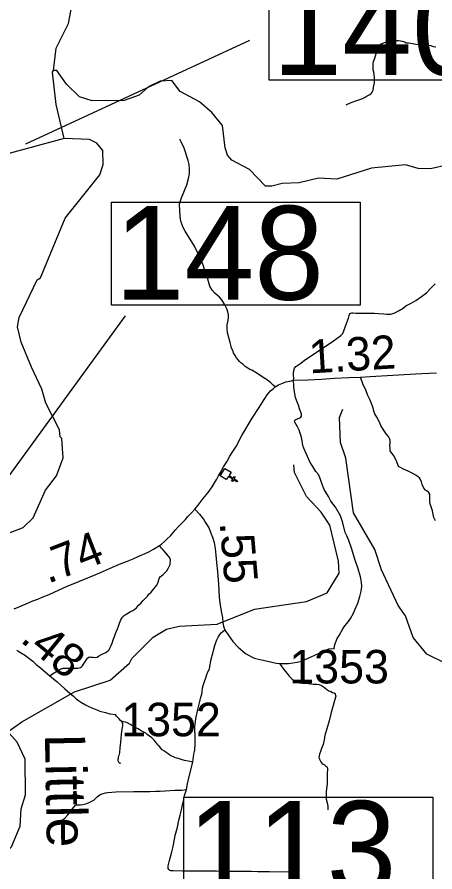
# Model space of a CAD drawing. Extents: x 2290615 to 2522933, y 819489 to 1012715.
# Drawn here: x 2328328 to 2334565, y 903675 to 916430 of the extents above; entities that cross this region are included whole.
import ezdxf

# ---------------------------------------------------------------- set-up
doc = ezdxf.new("R2010")
doc.units = 0
for name, color, linetype in [('Exist Cultural Church CELL', 7, 'Continuous'), ('Exist Hydrographic Creek Single Shore', 7, 'Continuous'), ('Exist Hydrographic Creek Single Shore Label', 7, 'Continuous'), ('Exist Hydrographic Misc Water Feature', 7, 'Continuous'), ('Exist Road Non-System Type 51', 7, 'Continuous'), ('Exist Road Secondary Mileage Hundredths English Label', 7, 'Continuous'), ('Exist Road Secondary Structure Standard Bridge Number Label', 7, 'Continuous'), ('Exist Road Secondary Type 51 Attributed', 7, 'Continuous'), ('Exist Road Secondary Type 51 Number Label', 7, 'Continuous')]:
    doc.layers.add(name, color=color, linetype=linetype)

msp = doc.modelspace()

# ---------------------------------------------------------------- linework, layer by layer
at = {"layer": 'Exist Cultural Church CELL'}
msp.add_lwpolyline([(2331521, 909638), (2331491, 909590), (2331555, 909549), (2331572, 909576), (2331585, 909568), (2331568, 909541), (2331619, 909508), (2331610, 909495), (2331560, 909527), (2331542, 909500), (2331529, 909509), (2331546, 909536), (2331482, 909577), (2331451, 909528), (2331361, 909585), (2331431, 909695)], close=True, dxfattribs=at)
at = {"layer": 'Exist Hydrographic Creek Single Shore'}
for points in [[(2328871, 915633), (2328909, 915966), (2329097, 916335), (2329199, 916894), (2329162, 917243), (2329102, 917352), (2328866, 917609), (2328739, 917846), (2328746, 917965), (2328828, 918057), (2329135, 918227), (2329382, 918404), (2329422, 918482), (2329413, 918613), (2329355, 918679)], [(2329032, 914619), (2328909, 915126), (2328854, 915609), (2328871, 915633)], [(2329032, 914619), (2328169, 914387)], [(2328335, 911807), (2328360, 911946), (2328629, 912508), (2328679, 912540), (2329044, 913428), (2329562, 914076), (2329611, 914232), (2329608, 914442), (2329516, 914550), (2329407, 914605), (2329032, 914619)], [(2327886, 908608), (2328417, 908813), (2328566, 908957), (2328753, 909369), (2328917, 909585), (2329014, 909852), (2328994, 910143), (2328969, 910169), (2328959, 910270), (2328755, 910668), (2328695, 910876), (2328541, 911208), (2328387, 911579), (2328335, 911807)], [(2325675, 904352), (2326165, 904408), (2326674, 904406), (2327058, 904326), (2327367, 904178), (2327812, 903859), (2327979, 903885), (2328145, 903954), (2328243, 904047), (2328374, 904357), (2328387, 904614), (2328452, 904823), (2328446, 905358), (2328327, 905613), (2328209, 905746), (2328208, 905778)]]:
    msp.add_lwpolyline(points, dxfattribs=at)
at = {"layer": 'Exist Hydrographic Misc Water Feature'}
for points in [[(2331799, 914155), (2331534, 914295), (2331467, 914371), (2331432, 914478), (2331395, 914811), (2331235, 915008), (2331050, 915164), (2330764, 915320), (2330638, 915486), (2330464, 915475), (2330290, 915389), (2330149, 915265), (2329925, 915187), (2329449, 915181), (2329258, 915238), (2329064, 915427), (2328920, 915635), (2328871, 915633)], [(2335149, 914154), (2334940, 914234), (2334765, 914224), (2334499, 914164), (2334316, 914169), (2334124, 914224), (2333616, 914177), (2333102, 914011), (2332826, 914026), (2332536, 913955), (2332286, 913945), (2332128, 913909), (2332036, 913908), (2331799, 914155)], [(2335796, 906582), (2335621, 906647), (2335136, 906772), (2334728, 906785), (2334443, 906924), (2334240, 907172), (2334128, 907495), (2334017, 907651), (2333769, 908180), (2333666, 908487), (2333351, 909035), (2333233, 909848), (2333155, 910081), (2333142, 910455), (2333191, 910581)], [(2331870, 907593), (2332650, 907710), (2332957, 907838), (2333137, 908131), (2333126, 908314), (2332995, 908847), (2332868, 909045), (2332648, 909276), (2332469, 909633), (2332459, 909747)], [(2328208, 905778), (2328398, 905914), (2329185, 906363), (2329716, 906536), (2330005, 906791), (2330038, 906858), (2330359, 907176), (2330558, 907296), (2330749, 907340), (2331315, 907370), (2331870, 907593)]]:
    msp.add_lwpolyline(points, dxfattribs=at)
at = {"layer": 'Exist Road Non-System Type 51'}
for points in [[(2333241, 915123), (2333313, 915154), (2333401, 915185), (2333475, 915210), (2333522, 915236), (2333553, 915253), (2333582, 915268), (2333609, 915285), (2333620, 915296), (2333630, 915312), (2333641, 915342), (2333648, 915383), (2333662, 915447), (2333664, 915483), (2333662, 915530), (2333657, 915576), (2333655, 915610), (2333643, 915641), (2333642, 915667), (2333642, 915695), (2333643, 915734), (2333649, 915769), (2333656, 915791), (2333666, 915816), (2333687, 915889), (2333705, 915949), (2333724, 916000), (2333751, 916028), (2333786, 916041), (2333815, 916052), (2333829, 916055), (2333869, 916059), (2333891, 916066), (2333914, 916070), (2333932, 916077), (2333949, 916080), (2333964, 916081), (2333988, 916083), (2334020, 916081), (2334049, 916078), (2334077, 916070), (2334109, 916060), (2334137, 916048), (2334173, 916046), (2334229, 916037), (2334282, 916028), (2334342, 916021), (2334390, 916016), (2334459, 916010), (2334502, 916004), (2334537, 915993), (2334577, 915986)], [(2332180, 910914), (2332150, 910937), (2332112, 910977), (2332053, 911020), (2332003, 911053), (2331908, 911118), (2331830, 911162), (2331804, 911174), (2331774, 911192), (2331733, 911217), (2331695, 911251), (2331667, 911269), (2331646, 911290), (2331626, 911318), (2331604, 911346), (2331582, 911380), (2331559, 911421), (2331547, 911453), (2331528, 911491), (2331520, 911535), (2331508, 911575), (2331495, 911631), (2331471, 911718), (2331465, 911786), (2331464, 911818), (2331465, 911840), (2331476, 911884), (2331482, 911938), (2331482, 911986), (2331475, 912034), (2331459, 912079), (2331430, 912137), (2331384, 912209), (2331347, 912252), (2331281, 912313), (2331242, 912357), (2331207, 912413), (2331164, 912552), (2331092, 912773), (2330975, 913014), (2330839, 913236), (2330808, 913290), (2330777, 913368), (2330767, 913416), (2330762, 913462), (2330756, 913534), (2330752, 913642), (2330780, 913734), (2330860, 913929), (2330892, 914041), (2330899, 914099), (2330901, 914163), (2330894, 914229), (2330881, 914292), (2330821, 914474), (2330778, 914571), (2330758, 914607)], [(2333724, 912008), (2333804, 912004), (2333847, 911998), (2333867, 911996), (2333886, 911996), (2333902, 911996), (2333924, 912002), (2333965, 912018), (2334031, 912051), (2334090, 912088), (2334133, 912121), (2334208, 912163), (2334278, 912202), (2334363, 912259), (2334437, 912317), (2334510, 912388), (2334549, 912431), (2334571, 912451)], [(2332243, 906786), (2332302, 906784), (2332378, 906784), (2332507, 906804), (2332573, 906821), (2332685, 906868), (2332772, 906907), (2332839, 906941), (2332929, 906981), (2332983, 907005), (2333027, 907008), (2333062, 907005), (2333067, 907049), (2333082, 907093), (2333107, 907158), (2333137, 907202), (2333191, 907301), (2333221, 907347), (2333274, 907410), (2333306, 907456), (2333349, 907535), (2333370, 907585), (2333413, 907687), (2333442, 907784), (2333463, 907866), (2333472, 907936), (2333469, 907998), (2333452, 908076), (2333417, 908195), (2333367, 908343), (2333321, 908504), (2333282, 908621), (2333250, 908688), (2333227, 908739), (2333189, 908884), (2333155, 908990), (2333080, 909119), (2333013, 909206), (2332974, 909275), (2332912, 909383), (2332875, 909470), (2332853, 909544), (2332826, 909604), (2332789, 909651), (2332740, 909723), (2332704, 909782), (2332665, 909872), (2332642, 909919), (2332609, 909997), (2332595, 910039), (2332576, 910137), (2332565, 910194), (2332540, 910268), (2332516, 910314), (2332472, 910387), (2332469, 910405), (2332473, 910418), (2332488, 910428), (2332549, 910448), (2332564, 910460), (2332572, 910475), (2332572, 910503), (2332564, 910534), (2332545, 910585), (2332527, 910638), (2332503, 910698), (2332484, 910755), (2332473, 910808), (2332466, 910875), (2332459, 910924), (2332455, 911011), (2332459, 911044), (2332456, 911080), (2332456, 911110), (2332460, 911158), (2332467, 911190), (2332488, 911217), (2332563, 911265), (2332620, 911311), (2332764, 911403), (2332904, 911499), (2333033, 911586), (2333161, 911680), (2333189, 911710), (2333226, 911801), (2333252, 911875), (2333273, 911939), (2333286, 911978), (2333288, 911990), (2333298, 912006), (2333308, 912010), (2333324, 912016), (2333345, 912016), (2333386, 912012), (2333443, 912014), (2333490, 912012), (2333537, 912010), (2333580, 912010), (2333663, 912010), (2333724, 912008)], [(2333899, 910116), (2333888, 910143), (2333872, 910170), (2333835, 910211), (2333798, 910269), (2333760, 910335), (2333739, 910387), (2333699, 910461), (2333668, 910511), (2333658, 910535), (2333638, 910609), (2333619, 910663), (2333594, 910725), (2333563, 910786), (2333529, 910876), (2333496, 910943), (2333456, 911059)], [(2334574, 908912), (2334550, 908963), (2334530, 909063), (2334491, 909181), (2334489, 909236), (2334490, 909310), (2334468, 909340), (2334425, 909371), (2334401, 909399), (2334376, 909458), (2334366, 909493), (2334348, 909529), (2334333, 909554), (2334303, 909576), (2334280, 909593), (2334237, 909618), (2334166, 909654), (2334094, 909685), (2334039, 909713), (2334023, 909724), (2334013, 909752), (2333985, 909819), (2333954, 909884), (2333899, 909960), (2333896, 910001), (2333892, 910034), (2333896, 910076), (2333899, 910116)], [(2328818, 906600), (2328856, 906628), (2328955, 906689), (2328995, 906708), (2329007, 906711), (2329018, 906713), (2329041, 906714), (2329081, 906715), (2329112, 906713), (2329140, 906712), (2329180, 906713), (2329211, 906713), (2329236, 906715), (2329256, 906722), (2329274, 906727), (2329289, 906736), (2329304, 906752), (2329318, 906775), (2329350, 906817), (2329381, 906863), (2329397, 906878), (2329410, 906883), (2329427, 906881), (2329462, 906877), (2329494, 906875), (2329522, 906881), (2329545, 906892), (2329586, 906920), (2329618, 906934), (2329644, 906944), (2329666, 906959), (2329678, 906969), (2329692, 906981), (2329702, 906989), (2329713, 907011), (2329733, 907051), (2329750, 907101), (2329764, 907138), (2329781, 907188), (2329797, 907230), (2329824, 907304), (2329840, 907344), (2329857, 907388), (2329875, 907435), (2329891, 907459), (2329902, 907475), (2329926, 907499), (2329958, 907521), (2329980, 907534), (2330023, 907560), (2330055, 907576), (2330083, 907595), (2330109, 907617), (2330142, 907653), (2330176, 907686), (2330208, 907724), (2330239, 907757), (2330274, 907789), (2330296, 907817), (2330328, 907851), (2330350, 907874), (2330370, 907898), (2330395, 907928), (2330413, 907954), (2330432, 907998), (2330446, 908053), (2330462, 908077), (2330487, 908097), (2330507, 908113), (2330533, 908136), (2330550, 908151), (2330565, 908168), (2330584, 908202), (2330600, 908230), (2330612, 908260), (2330615, 908284), (2330619, 908310), (2330619, 908330), (2330613, 908348), (2330607, 908362), (2330536, 908447), (2330503, 908487), (2330483, 908507), (2330453, 908544)], [(2330951, 905310), (2330968, 905431), (2330979, 905493), (2330983, 905525), (2330987, 905553), (2330988, 905593), (2330988, 905629), (2330987, 905663), (2330985, 905705), (2330985, 905735), (2330982, 905771), (2330982, 905809), (2330981, 905843), (2330985, 905877), (2330989, 905919), (2330998, 905965), (2331008, 906011), (2331015, 906049), (2331027, 906099), (2331034, 906136), (2331046, 906180), (2331057, 906220), (2331071, 906282), (2331085, 906327), (2331092, 906364), (2331097, 906423), (2331103, 906456), (2331118, 906500), (2331130, 906529), (2331140, 906557), (2331149, 906585), (2331161, 906619), (2331176, 906658), (2331188, 906681), (2331200, 906710), (2331209, 906763), (2331214, 906797), (2331219, 906829), (2331236, 906884), (2331241, 906904), (2331245, 906919), (2331248, 906936), (2331258, 906978), (2331278, 907052), (2331294, 907097), (2331309, 907138), (2331328, 907180), (2331354, 907218), (2331373, 907241), (2331397, 907263), (2331428, 907289)], [(2332243, 906786), (2332270, 906752), (2332293, 906715), (2332330, 906671), (2332357, 906633), (2332391, 906597), (2332434, 906553), (2332470, 906527), (2332507, 906510), (2332541, 906498), (2332590, 906491), (2332671, 906484), (2332752, 906478), (2332800, 906478), (2332836, 906472), (2332871, 906455), (2332916, 906425), (2332949, 906397), (2332980, 906379), (2333010, 906366), (2333037, 906354), (2333061, 906346), (2333075, 906335), (2333078, 906324), (2333081, 906312), (2333084, 906296), (2333081, 906284), (2333070, 906245), (2333036, 906122), (2333010, 906035), (2332985, 905931), (2332949, 905809), (2332926, 905728), (2332918, 905684), (2332918, 905669), (2332913, 905646), (2332901, 905602), (2332895, 905574), (2332884, 905540), (2332874, 905514), (2332859, 905472), (2332843, 905430), (2332836, 905403), (2332833, 905385), (2332836, 905371), (2332840, 905355), (2332850, 905336), (2332862, 905316), (2332878, 905298), (2332899, 905284), (2332918, 905271), (2332933, 905259), (2332944, 905249), (2332955, 905237), (2332960, 905218), (2332963, 905200), (2332957, 905155), (2332958, 905086), (2332958, 905035), (2332954, 904988), (2332943, 904874), (2332941, 904785), (2332943, 904759), (2332957, 904703), (2332966, 904656), (2332968, 904599)], [(2329872, 905934), (2329852, 905957), (2329832, 905981), (2329811, 905999), (2329799, 906022)], [(2329872, 905934), (2329889, 905912), (2329897, 905900), (2329900, 905893), (2329900, 905879), (2329900, 905856), (2329891, 905803), (2329882, 905730), (2329878, 905670), (2329871, 905608), (2329862, 905530), (2329854, 905451), (2329846, 905413), (2329838, 905391), (2329834, 905367), (2329832, 905350), (2329832, 905335), (2329836, 905325), (2329841, 905315), (2329846, 905307), (2329853, 905303), (2329861, 905300), (2329871, 905297)], [(2330951, 905310), (2330880, 905328), (2330827, 905338), (2330777, 905351), (2330737, 905365), (2330707, 905374), (2330683, 905384), (2330638, 905404), (2330610, 905417), (2330582, 905437), (2330552, 905455), (2330528, 905476), (2330495, 905498), (2330471, 905522), (2330455, 905544), (2330431, 905567), (2330417, 905587), (2330396, 905615), (2330378, 905637), (2330362, 905652), (2330340, 905674), (2330303, 905702), (2330271, 905724), (2330247, 905743), (2330211, 905763), (2330170, 905786), (2330134, 905808), (2330102, 905824), (2330071, 905841), (2330046, 905856), (2330021, 905872), (2329998, 905883), (2329980, 905894), (2329959, 905906), (2329944, 905911), (2329917, 905916), (2329888, 905926), (2329881, 905929), (2329872, 905934)], [(2330855, 904904), (2330873, 904991), (2330896, 905096), (2330951, 905310)], [(2328851, 904353), (2328882, 904373), (2328918, 904386), (2328949, 904406), (2328989, 904439), (2329045, 904484), (2329087, 904524), (2329111, 904555), (2329149, 904611), (2329179, 904648), (2329198, 904670), (2329216, 904677), (2329238, 904676), (2329274, 904677), (2329310, 904682), (2329369, 904694), (2329403, 904710), (2329471, 904747), (2329525, 904793), (2329569, 904829), (2329611, 904847), (2329648, 904855), (2329682, 904861), (2329741, 904864), (2329804, 904869), (2330070, 904876), (2330152, 904875), (2330308, 904876), (2330394, 904879), (2330464, 904882), (2330538, 904883), (2330684, 904892), (2330788, 904895), (2330855, 904904)], [(2332489, 903671), (2332097, 903675), (2331914, 903674), (2331824, 903683), (2331742, 903680), (2331411, 903682), (2331303, 903687), (2331061, 903685), (2330797, 903686), (2330659, 903690), (2330621, 903692), (2330607, 903698), (2330591, 903710), (2330584, 903726), (2330584, 903740), (2330584, 903764), (2330605, 903846), (2330619, 903900), (2330636, 903972), (2330655, 904056), (2330689, 904217), (2330720, 904343), (2330743, 904447), (2330760, 904521), (2330781, 904603), (2330796, 904678), (2330815, 904756), (2330829, 904816), (2330855, 904904)]]:
    msp.add_lwpolyline(points, dxfattribs=at)
at = {"layer": 'Exist Road Secondary Structure Standard Bridge Number Label'}
msp.add_line((2328459, 914540), (2331804, 916084), dxfattribs=at)
for points in [[(2332090, 917024), (2335806, 917024), (2335806, 915487), (2332090, 915487)], [(2329735, 913671), (2333451, 913671), (2333451, 912134), (2329735, 912134)], [(2330816, 904791), (2334532, 904791), (2334532, 903255), (2330816, 903255)]]:
    msp.add_lwpolyline(points, close=True, dxfattribs=at)
msp.add_lwpolyline([(2327020, 907036), (2328047, 909367), (2329944, 911974)], dxfattribs=at)
at = {"layer": 'Exist Road Secondary Type 51 Attributed'}
for points in [[(2330981, 909090), (2331031, 909148), (2331106, 909245), (2331179, 909335), (2331238, 909421), (2331282, 909493), (2331307, 909534), (2331336, 909585), (2331363, 909635), (2331409, 909717), (2331457, 909795), (2331504, 909880), (2331539, 909934), (2331598, 910024), (2331685, 910188), (2331838, 910447), (2331940, 910605), (2332017, 910726), (2332062, 910796), (2332109, 910851), (2332149, 910885), (2332180, 910914), (2332228, 910944), (2332278, 910965), (2332339, 910987), (2332397, 911000), (2332455, 911011), (2332675, 911017), (2332871, 911028), (2333067, 911042), (2333278, 911051), (2333456, 911059), (2333598, 911066), (2333852, 911081), (2334104, 911097), (2334369, 911112), (2334589, 911124)], [(2328286, 907599), (2328370, 907636), (2328471, 907681), (2328562, 907718), (2328635, 907747), (2328703, 907775), (2328805, 907812), (2328957, 907884), (2329066, 907933), (2329250, 908008), (2329502, 908113), (2329562, 908140), (2329617, 908164), (2329708, 908204), (2329787, 908238), (2329857, 908265), (2329920, 908290), (2329962, 908307), (2330062, 908348), (2330143, 908384), (2330239, 908426), (2330292, 908451), (2330363, 908490), (2330387, 908504), (2330453, 908544), (2330484, 908567), (2330531, 908608), (2330565, 908640), (2330620, 908692), (2330693, 908781), (2330739, 908829), (2330786, 908877), (2330840, 908933), (2330876, 908976), (2330934, 909038), (2330981, 909090)], [(2330981, 909090), (2331050, 909011), (2331089, 908961), (2331107, 908943), (2331120, 908924), (2331127, 908909), (2331166, 908847), (2331193, 908800), (2331222, 908727), (2331245, 908669), (2331270, 908589), (2331285, 908499), (2331294, 908400), (2331304, 908291), (2331317, 908150), (2331332, 907967), (2331346, 907776), (2331353, 907692), (2331381, 907537), (2331394, 907473), (2331401, 907393), (2331409, 907340), (2331424, 907298), (2331445, 907260), (2331549, 907112), (2331627, 907030), (2331698, 906967), (2331737, 906934), (2331803, 906897), (2331849, 906873), (2331886, 906861), (2331975, 906838), (2332093, 906814), (2332197, 906791), (2332243, 906786)], [(2328323, 906984), (2328355, 906966), (2328403, 906934), (2328452, 906902), (2328502, 906865), (2328563, 906818), (2328610, 906772), (2328676, 906721), (2328787, 906625), (2328818, 906600), (2328924, 906513), (2329042, 906405), (2329117, 906342), (2329168, 906296), (2329209, 906259), (2329246, 906231), (2329289, 906201), (2329349, 906167), (2329401, 906142), (2329442, 906123), (2329516, 906092), (2329564, 906073), (2329648, 906053), (2329712, 906035), (2329799, 906022)]]:
    msp.add_lwpolyline(points, dxfattribs=at)

# ---------------------------------------------------------------- texts
at = {"layer": 'Exist Hydrographic Creek Single Shore Label'}
msp.add_text('Little', height=600, rotation=271.0725, dxfattribs=at).set_placement((2328742, 905731))
at = {"layer": 'Exist Road Secondary Mileage Hundredths English Label'}
for s, rotation, p in [('1.32', 3.381, (2332696, 911113)), ('.55', 274.7941, (2331351, 908887)), ('.74', 21.2047, (2328788, 907972)), ('.48', 320.8705, (2328359, 907120))]:
    msp.add_text(s, height=500, rotation=rotation, dxfattribs=at).set_placement(p)
at = {"layer": 'Exist Road Secondary Structure Standard Bridge Number Label'}
for s, p in [('140', (2332140, 915566)), ('148', (2329785, 912213)), ('113', (2330866, 903334))]:
    msp.add_text(s, height=1400, dxfattribs=at).set_placement(p)
at = {"layer": 'Exist Road Secondary Type 51 Number Label'}
for s, p in [('1353', (2332391, 906487)), ('1352', (2329882, 905699))]:
    msp.add_text(s, height=500, rotation=360, dxfattribs=at).set_placement(p)

doc.saveas('drawing.dxf')
